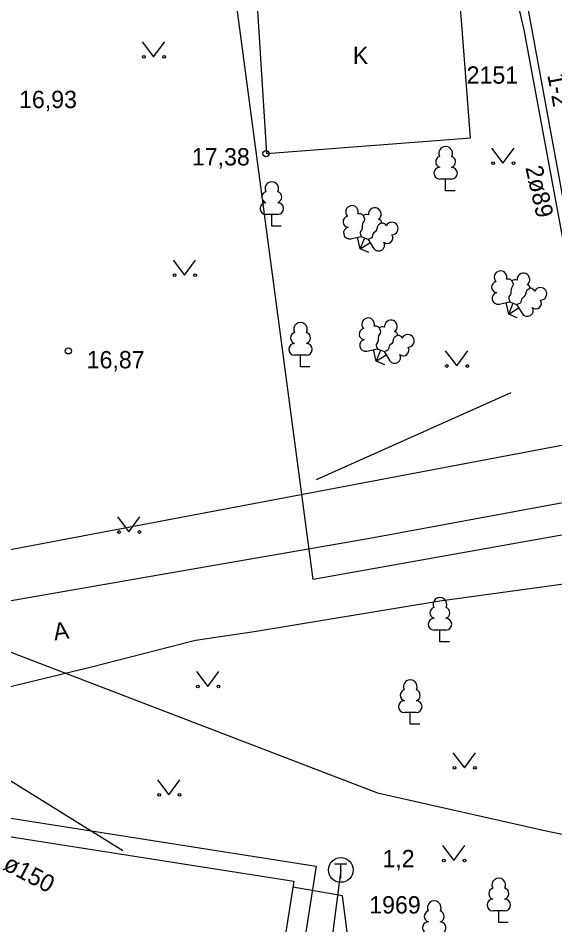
# Model space of a CAD drawing. Extents: x 713497 to 713863, y 6590062 to 6590327.
# Drawn here: x 713601.63 to 713623.33, y 6590062.3 to 6590099.22 of the extents above; entities that cross this region are included whole.
import ezdxf

# ---------------------------------------------------------------- set-up
doc = ezdxf.new("R2010")
doc.units = 0
for name, color, linetype in [('AED', 7, 'Continuous'), ('HALJASTUS', 7, 'Continuous'), ('HOONE', 7, 'Continuous'), ('KAEVU_NR', 7, 'Continuous'), ('KORGUS', 7, 'Continuous'), ('MPKAABEL', 7, 'Continuous'), ('PUU', 7, 'Continuous'), ('SIKAEV', 7, 'Continuous'), ('SITRASS', 7, 'Continuous'), ('TEE', 7, 'Continuous'), ('TKAEV', 7, 'Continuous'), ('TORU NR', 7, 'Continuous'), ('TTRASS', 7, 'Continuous'), ('Слой 1', 7, 'Continuous')]:
    doc.layers.add(name, color=color, linetype=linetype)

msp = doc.modelspace()

# ---------------------------------------------------------------- linework, layer by layer
at = {"layer": 'AED'}
msp.add_lwpolyline([(713614.939, 6590062.302), (713614.75, 6590063.75), (713612.737, 6590064.105)], dxfattribs=at)
at = {"layer": 'HALJASTUS'}
for p, q in [((713606.647, 6590098.277), (713607.11, 6590097.67)), ((713607.11, 6590097.67), (713607.556, 6590098.277)), ((713620.777, 6590093.977), (713621.24, 6590093.37)), ((713621.24, 6590093.37), (713621.686, 6590093.977)), ((713607.897, 6590089.447), (713608.36, 6590088.84)), ((713608.36, 6590088.84), (713608.806, 6590089.447)), ((713618.907, 6590085.777), (713619.37, 6590085.17)), ((713619.37, 6590085.17), (713619.816, 6590085.777)), ((713605.647, 6590079.067), (713606.11, 6590078.46)), ((713606.11, 6590078.46), (713606.556, 6590079.067)), ((713608.837, 6590072.817), (713609.3, 6590072.21)), ((713609.3, 6590072.21), (713609.746, 6590072.817)), ((713619.217, 6590069.537), (713619.68, 6590068.93)), ((713619.68, 6590068.93), (713620.126, 6590069.537)), ((713607.267, 6590068.447), (713607.73, 6590067.84)), ((713607.73, 6590067.84), (713608.176, 6590068.447)), ((713618.787, 6590065.787), (713619.25, 6590065.18)), ((713619.25, 6590065.18), (713619.696, 6590065.787))]:
    msp.add_line(p, q, dxfattribs=at)
msp.add_lwpolyline([(713621.56, 6590084.08), (713613.69, 6590080.57)], dxfattribs=at)
for centre in [(713606.709, 6590097.67), (713607.538, 6590097.67), (713620.839, 6590093.37), (713621.668, 6590093.37), (713607.959, 6590088.84), (713608.788, 6590088.84), (713618.969, 6590085.17), (713619.798, 6590085.17), (713605.709, 6590078.46), (713606.538, 6590078.46), (713608.899, 6590072.21), (713609.728, 6590072.21), (713619.279, 6590068.93), (713620.108, 6590068.93), (713607.329, 6590067.84), (713608.158, 6590067.84), (713618.849, 6590065.18), (713619.678, 6590065.18)]:
    msp.add_circle(centre, 0.055, dxfattribs=at)
at = {"layer": 'HOONE'}
for points in [[(713611.19, 6590101.46), (713611.67, 6590093.76), (713619.92, 6590094.39), (713619.33, 6590102.14), (713611.19, 6590101.46)], [(713599.945, 6590062.302), (713600.565, 6590066.262), (713612.776, 6590064.349)], [(713612.776, 6590064.349), (713612.455, 6590062.302)]]:
    msp.add_lwpolyline(points, dxfattribs=at)
at = {"layer": 'KORGUS'}
for centre in [(713611.65, 6590093.75), (713603.66, 6590085.78)]:
    msp.add_circle(centre, 0.125, dxfattribs=at)
at = {"layer": 'MPKAABEL'}
msp.add_lwpolyline([(713579.83, 6590081.77), (713605.87, 6590065.59)], dxfattribs=at)
at = {"layer": 'PUU'}
for p, q in [((713619.16, 6590092.725), (713618.68, 6590092.725)), ((713618.92, 6590092.25), (713618.92, 6590092.725)), ((713619.3, 6590092.25), (713618.92, 6590092.25)), ((713612.13, 6590091.295), (713611.65, 6590091.295)), ((713611.89, 6590090.82), (713611.89, 6590091.295)), ((713612.27, 6590090.82), (713611.89, 6590090.82)), ((713615.077, 6590090.312), (713615.508, 6590090.406)), ((713615.46, 6590089.91), (713615.358, 6590090.372)), ((713615.46, 6590089.91), (713615.646, 6590090.347)), ((713615.508, 6590090.406), (713615.78, 6590090.29)), ((713615.78, 6590090.29), (713616.015, 6590089.923)), ((713615.46, 6590089.91), (713615.861, 6590090.163)), ((713615.81, 6590089.761), (713615.46, 6590089.91)), ((713621.087, 6590087.672), (713621.518, 6590087.766)), ((713621.47, 6590087.27), (713621.368, 6590087.732)), ((713621.47, 6590087.27), (713621.656, 6590087.707)), ((713621.518, 6590087.766), (713621.79, 6590087.65)), ((713621.47, 6590087.27), (713621.871, 6590087.523)), ((713621.79, 6590087.65), (713622.025, 6590087.283)), ((713621.82, 6590087.121), (713621.47, 6590087.27)), ((713615.727, 6590085.772), (713616.158, 6590085.866)), ((713616.158, 6590085.866), (713616.43, 6590085.75)), ((713613.29, 6590085.605), (713612.81, 6590085.605)), ((713613.05, 6590085.13), (713613.05, 6590085.605)), ((713616.11, 6590085.37), (713616.008, 6590085.832)), ((713616.11, 6590085.37), (713616.296, 6590085.807)), ((713616.11, 6590085.37), (713616.511, 6590085.623)), ((713616.43, 6590085.75), (713616.665, 6590085.383)), ((713613.43, 6590085.13), (713613.05, 6590085.13)), ((713616.46, 6590085.221), (713616.11, 6590085.37)), ((713618.93, 6590074.495), (713618.45, 6590074.495)), ((713618.69, 6590074.02), (713618.69, 6590074.495)), ((713619.07, 6590074.02), (713618.69, 6590074.02)), ((713617.73, 6590071.165), (713617.25, 6590071.165)), ((713617.49, 6590070.69), (713617.49, 6590071.165)), ((713617.87, 6590070.69), (713617.49, 6590070.69)), ((713621.31, 6590063.145), (713620.83, 6590063.145)), ((713621.07, 6590062.67), (713621.07, 6590063.145)), ((713621.45, 6590062.67), (713621.07, 6590062.67))]:
    msp.add_line(p, q, dxfattribs=at)
for points in [[(713615.586, 6590091.256), (713615.64, 6590091.122), (713615.642, 6590091.088), (713615.62, 6590091.038), (713615.571, 6590090.961), (713615.554, 6590090.919), (713615.541, 6590090.838), (713615.542, 6590090.739), (713615.534, 6590090.694), (713615.511, 6590090.655), (713615.472, 6590090.601), (713615.46, 6590090.573), (713615.463, 6590090.528), (713615.474, 6590090.491), (713615.508, 6590090.406)], [(713616.342, 6590090.949), (713616.21, 6590090.878), (713616.185, 6590090.857), (713616.163, 6590090.806), (713616.141, 6590090.717), (713616.128, 6590090.674), (713616.079, 6590090.608), (713616.006, 6590090.541), (713615.98, 6590090.504), (713615.967, 6590090.46), (713615.955, 6590090.395), (713615.943, 6590090.367), (713615.909, 6590090.338), (713615.874, 6590090.32), (713615.784, 6590090.288)], [(713621.596, 6590088.616), (713621.65, 6590088.482), (713621.652, 6590088.448), (713621.63, 6590088.398), (713621.581, 6590088.321), (713621.564, 6590088.279), (713621.551, 6590088.198), (713621.552, 6590088.099), (713621.544, 6590088.054), (713621.521, 6590088.015), (713621.482, 6590087.961), (713621.47, 6590087.933), (713621.473, 6590087.888), (713621.484, 6590087.851), (713621.518, 6590087.766)], [(713622.352, 6590088.309), (713622.22, 6590088.238), (713622.195, 6590088.217), (713622.173, 6590088.166), (713622.151, 6590088.077), (713622.138, 6590088.034), (713622.089, 6590087.968), (713622.016, 6590087.901), (713621.99, 6590087.864), (713621.977, 6590087.82), (713621.965, 6590087.755), (713621.953, 6590087.727), (713621.919, 6590087.698), (713621.884, 6590087.68), (713621.794, 6590087.648)], [(713616.236, 6590086.716), (713616.29, 6590086.582), (713616.292, 6590086.548), (713616.27, 6590086.498), (713616.221, 6590086.421), (713616.204, 6590086.379), (713616.191, 6590086.298), (713616.192, 6590086.199), (713616.184, 6590086.154), (713616.161, 6590086.115), (713616.122, 6590086.061), (713616.11, 6590086.033), (713616.113, 6590085.988), (713616.124, 6590085.951), (713616.158, 6590085.866)], [(713616.992, 6590086.409), (713616.86, 6590086.338), (713616.835, 6590086.317), (713616.813, 6590086.266), (713616.791, 6590086.177), (713616.778, 6590086.134), (713616.729, 6590086.068), (713616.656, 6590086.001), (713616.63, 6590085.964), (713616.617, 6590085.92), (713616.605, 6590085.855), (713616.593, 6590085.827), (713616.559, 6590085.798), (713616.524, 6590085.78), (713616.434, 6590085.748)]]:
    msp.add_lwpolyline(points, dxfattribs=at)
for centre, radius, start, end in [((713618.92, 6590093.77), 0.277, 332.5799, 207.4201), ((713618.75, 6590093.423), 0.233, 109.0217, 253.1415), ((713619.09, 6590093.423), 0.233, 286.8508, 70.9859), ((713618.683, 6590092.962), 0.238, 90.0016, 269.3953), ((713619.157, 6590092.962), 0.238, 270.6047, 89.9984), ((713611.89, 6590092.34), 0.277, 332.5799, 207.4201), ((713611.72, 6590091.993), 0.233, 109.0217, 253.1415), ((713612.06, 6590091.993), 0.233, 286.8508, 70.9859), ((713611.653, 6590091.532), 0.238, 90.0016, 269.3953), ((713612.127, 6590091.532), 0.238, 270.6047, 89.9984), ((713615.133, 6590091.394), 0.256, 102.436, 223.4506), ((713615.133, 6590091.394), 0.256, 341.4189, 102.4335), ((713616.056, 6590091.308), 0.256, 66.8983, 187.9129), ((713616.056, 6590091.308), 0.256, 305.8812, 66.8958), ((713614.995, 6590091), 0.224, 102.3637, 265.432), ((713615.436, 6590091.121), 0.202, 42.1353, 107.6383), ((713615.708, 6590091.095), 0.202, 61.6935, 127.1965), ((713616.144, 6590090.909), 0.202, 11.2827, 72.1006), ((713615.028, 6590090.544), 0.237, 102.4347, 282.4337), ((713616.335, 6590090.747), 0.202, 27.2143, 88.0322), ((713616.743, 6590090.725), 0.256, 32.4191, 153.4337), ((713616.743, 6590090.725), 0.256, 271.402, 32.4166), ((713616.56, 6590090.349), 0.224, 229.4206, 32.4889), ((713616.214, 6590090.051), 0.237, 212.4189, 32.4178), ((713621.143, 6590088.754), 0.256, 102.436, 223.4506), ((713621.143, 6590088.754), 0.256, 341.4189, 102.4335), ((713622.066, 6590088.668), 0.256, 66.8983, 187.9129), ((713622.066, 6590088.668), 0.256, 305.8812, 66.8958), ((713621.005, 6590088.36), 0.224, 102.3637, 265.432), ((713621.446, 6590088.481), 0.202, 42.1353, 107.6383), ((713621.718, 6590088.455), 0.202, 61.6935, 127.1965), ((713622.154, 6590088.269), 0.202, 11.2827, 72.1006), ((713621.038, 6590087.904), 0.237, 102.4347, 282.4337), ((713622.345, 6590088.107), 0.202, 27.2143, 88.0322), ((713622.753, 6590088.085), 0.256, 32.4191, 153.4337), ((713622.753, 6590088.085), 0.256, 271.402, 32.4166), ((713622.57, 6590087.709), 0.224, 229.4206, 32.4889), ((713622.224, 6590087.411), 0.237, 212.4189, 32.4178), ((713615.783, 6590086.854), 0.256, 102.436, 223.4506), ((713615.783, 6590086.854), 0.256, 341.4189, 102.4335), ((713616.706, 6590086.768), 0.256, 66.8983, 187.9129), ((713616.706, 6590086.768), 0.256, 305.8812, 66.8958), ((713613.05, 6590086.65), 0.277, 332.5799, 207.4201), ((713615.645, 6590086.46), 0.224, 102.3637, 265.432), ((713616.086, 6590086.581), 0.202, 42.1353, 107.6383), ((713616.358, 6590086.555), 0.202, 61.6935, 127.1965), ((713612.88, 6590086.303), 0.233, 109.0217, 253.1415), ((713613.22, 6590086.303), 0.233, 286.8508, 70.9859), ((713615.678, 6590086.004), 0.237, 102.4347, 282.4337), ((713616.794, 6590086.369), 0.202, 11.2827, 72.1006), ((713616.985, 6590086.207), 0.202, 27.2143, 88.0322), ((713617.393, 6590086.185), 0.256, 32.4191, 153.4337), ((713617.393, 6590086.185), 0.256, 271.402, 32.4166), ((713612.813, 6590085.842), 0.238, 90.0016, 269.3953), ((713613.287, 6590085.842), 0.238, 270.6047, 89.9984), ((713617.21, 6590085.809), 0.224, 229.4206, 32.4889), ((713616.864, 6590085.511), 0.237, 212.4189, 32.4178), ((713618.69, 6590075.54), 0.277, 332.5799, 207.4201), ((713618.52, 6590075.193), 0.233, 109.0217, 253.1415), ((713618.86, 6590075.193), 0.233, 286.8508, 70.9859), ((713618.453, 6590074.732), 0.238, 90.0016, 269.3953), ((713618.927, 6590074.732), 0.238, 270.6047, 89.9984), ((713617.49, 6590072.21), 0.277, 332.5799, 207.4201), ((713617.32, 6590071.863), 0.233, 109.0217, 253.1415), ((713617.66, 6590071.863), 0.233, 286.8508, 70.9859), ((713617.253, 6590071.402), 0.238, 90.0016, 269.3953), ((713617.727, 6590071.402), 0.238, 270.6047, 89.9984), ((713621.07, 6590064.19), 0.277, 332.5799, 207.4201), ((713620.9, 6590063.843), 0.233, 109.0217, 253.1415), ((713621.24, 6590063.843), 0.233, 286.8508, 70.9859), ((713618.46, 6590063.27), 0.277, 332.5799, 207.4201), ((713620.833, 6590063.382), 0.238, 90.0016, 269.3953), ((713621.307, 6590063.382), 0.238, 270.6047, 89.9984), ((713618.29, 6590062.923), 0.233, 109.0217, 253.1415), ((713618.63, 6590062.923), 0.233, 286.8508, 70.9859), ((713618.223, 6590062.462), 0.238, 90.0016, 222.3719), ((713618.697, 6590062.462), 0.238, 317.6281, 89.9984)]:
    msp.add_arc(centre, radius, start, end, dxfattribs=at)
at = {"layer": 'SITRASS'}
for points in [[(713562.8, 6590094.1), (713563.18, 6590093.71), (713583.91, 6590074.65), (713584.41, 6590074.66), (713599.94, 6590077.49), (713634.666, 6590084.052), (713650.229, 6590087.502)], [(713583.71, 6590080.35), (713616.17, 6590067.91), (713623.11, 6590066.35), (713631.144, 6590064.714), (713634.16, 6590064.1)]]:
    msp.add_lwpolyline(points, dxfattribs=at)
at = {"layer": 'TEE'}
for points in [[(713593.07, 6590074.25), (713606.92, 6590076.66), (713615.86, 6590078.21), (713625.56, 6590080), (713629.1, 6590080.59), (713628.94, 6590081.56), (713629.78, 6590081.87), (713630, 6590082.07), (713629.42, 6590086.4), (713627.4, 6590097.45), (713625.89, 6590107), (713625.27, 6590109.92), (713623.87, 6590118.38), (713622.747, 6590124.744)], [(713630.917, 6590062.302), (713630.802, 6590062.998), (713630.719, 6590063.593), (713629.2, 6590074.55), (713628.81, 6590075.6), (713628.07, 6590076.37), (713627.04, 6590076.7), (713626.1, 6590076.71), (713623.5, 6590076.33), (713618.68, 6590075.67), (713611.17, 6590074.43), (713608.8, 6590074.08), (713604.6, 6590072.99), (713595.688, 6590070.834), (713593.307, 6590063.838), (713593.646, 6590062.302)], [(713599.196, 6590062.302), (713599.948, 6590067.107), (713613.681, 6590064.956)], [(713613.681, 6590064.956), (713613.265, 6590062.302)]]:
    msp.add_lwpolyline(points, dxfattribs=at)
at = {"layer": 'TKAEV'}
for p, q in [((713614.43, 6590065.05), (713614.93, 6590065.05)), ((713614.68, 6590064.45), (713614.68, 6590065.05))]:
    msp.add_line(p, q, dxfattribs=at)
msp.add_circle((713614.68, 6590064.8), 0.5, dxfattribs=at)
at = {"layer": 'TTRASS'}
for points in [[(713613.075, 6590150.266), (713615.084, 6590138.478), (713615.264, 6590137.579), (713615.435, 6590136.329), (713617.771, 6590124.577), (713619.837, 6590112.816), (713620.154, 6590110.967), (713620.346, 6590109.864), (713622.125, 6590100.294), (713622.326, 6590099.19), (713624.508, 6590087.316), (713626.564, 6590075.48), (713628.463, 6590064.543), (713628.657, 6590063.675), (713628.894, 6590062.458), (713628.92, 6590062.302)], [(713612.943, 6590150.015), (713614.851, 6590138.172), (713615.046, 6590137.323), (713615.295, 6590136.103), (713617.421, 6590124.308), (713619.624, 6590112.478), (713619.897, 6590111.234), (713620.038, 6590110.045), (713621.824, 6590099.845), (713622.082, 6590098.761), (713624.27, 6590086.994), (713626.319, 6590075.085), (713628.187, 6590064.517), (713628.385, 6590063.541), (713628.62, 6590062.302)], [(713614.68, 6590064.8), (713614.357, 6590062.302)]]:
    msp.add_lwpolyline(points, dxfattribs=at)
at = {"layer": 'Слой 1'}
msp.add_lwpolyline([(713608.74, 6590112.77), (713610.92, 6590113.06), (713610.16, 6590116.83), (713646.6, 6590123.47), (713654.08, 6590083.76), (713613.56, 6590076.54)], close=True, dxfattribs=at)

# ---------------------------------------------------------------- texts
at = {"layer": 'HOONE'}
msp.add_text('K', height=0.7, rotation=0.0289, dxfattribs=at).set_placement((713615.167, 6590097.37))
at = {"layer": 'KAEVU_NR'}
msp.add_text('1969', height=0.7, dxfattribs=at).set_placement((713615.83, 6590063.04))
at = {"layer": 'KORGUS'}
for s, p in [('16,93', (713601.666, 6590095.595)), ('17,38', (713608.656, 6590093.275)), ('16,87', (713604.403, 6590085.075))]:
    msp.add_text(s, height=0.7, dxfattribs=at).set_placement(p)
at = {"layer": 'SIKAEV'}
msp.add_text('2151', height=0.7, dxfattribs=at).set_placement((713619.77, 6590096.58))
at = {"layer": 'TEE'}
msp.add_text('A', height=0.7, rotation=8.0794, dxfattribs=at).set_placement((713603.102, 6590074.072))
at = {"layer": 'TORU NR'}
for s, rotation, p in [('1-2', 280.6996, (713623.032, 6590096.931)), ('2ø89', 282.8268, (713622.142, 6590093.189)), ('ø150', 332.3005, (713600.974, 6590064.842))]:
    msp.add_text(s, height=0.7, rotation=rotation, dxfattribs=at).set_placement(p)
msp.add_text('1,2', height=0.7, dxfattribs=at).set_placement((713616.364, 6590064.91))

doc.saveas('drawing.dxf')
